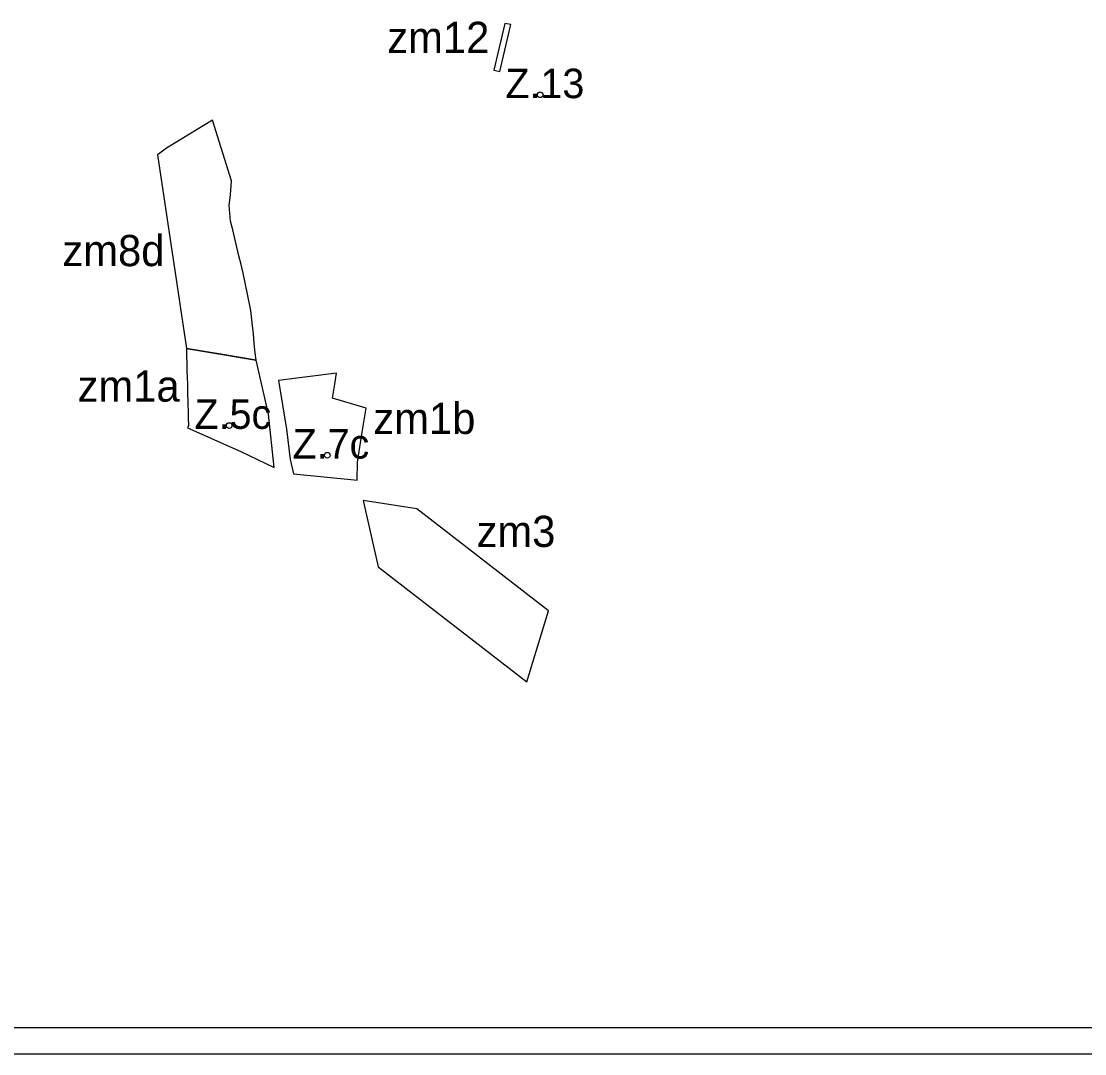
# Model space of a CAD drawing. Extents: x -555210 to -552521, y -1185897 to -1183927.
# Drawn here: x -554479 to -553865, y -1185897 to -1185302 of the extents above; entities that cross this region are included whole.
import ezdxf

# ---------------------------------------------------------------- set-up
doc = ezdxf.new("R2010")
doc.units = 0
for name, color, linetype in [('LEG_2b', 7, 'Continuous'), ('ram_5000', 7, 'Continuous'), ('stav_OV', 7, 'Continuous'), ('stav_PU', 7, 'Continuous'), ('stav_SV', 7, 'Continuous'), ('stav_SX', 7, 'Continuous'), ('stav_ZZ', 7, 'Continuous')]:
    doc.layers.add(name, color=color, linetype=linetype)

msp = doc.modelspace()

# ---------------------------------------------------------------- linework, layer by layer
at = {"layer": 'LEG_2b'}
for centre in [(-554179.27, -1185344.19), (-554358.57, -1185534.95), (-554302.04, -1185552.12)]:
    msp.add_circle(centre, 1.64, dxfattribs=at)
at = {"layer": 'ram_5000'}
for p, q in [((-554199.59, -1185303), (-554205.92, -1185330.05)), ((-554202.48, -1185330.72), (-554196.15, -1185303.69)), ((-554196.15, -1185303.69), (-554199.59, -1185303)), ((-554205.92, -1185330.05), (-554202.48, -1185330.72)), ((-554368.27, -1185358.89), (-554394.81, -1185374.96)), ((-554357.24, -1185393.87), (-554368.27, -1185358.89)), ((-554394.81, -1185374.96), (-554398.64, -1185377.82)), ((-554398.64, -1185377.82), (-554399.87, -1185378.78)), ((-554399.87, -1185378.78), (-554383.32, -1185490.61)), ((-554358.1, -1185403.56), (-554357.73, -1185399.4)), ((-554357.73, -1185399.4), (-554357.24, -1185393.87)), ((-554358.55, -1185407.8), (-554358.1, -1185403.56)), ((-554358.24, -1185412.39), (-554358.55, -1185407.8)), ((-554357.86, -1185417.02), (-554358.24, -1185412.39)), ((-554356.48, -1185422.06), (-554357.86, -1185417.02)), ((-554355.39, -1185427.08), (-554356.48, -1185422.06)), ((-554354.3, -1185432.1), (-554355.39, -1185427.08)), ((-554353.02, -1185437.14), (-554354.3, -1185432.1)), ((-554351.77, -1185442.03), (-554353.02, -1185437.14)), ((-554345.29, -1185475.74), (-554346.15, -1185468.55)), ((-554344.6, -1185481.98), (-554345.29, -1185475.74)), ((-554344.16, -1185487.64), (-554344.6, -1185481.98)), ((-554371.71, -1185492.51), (-554383.32, -1185490.61)), ((-554383.32, -1185490.61), (-554371.71, -1185492.51)), ((-554343.59, -1185493), (-554344.16, -1185487.64)), ((-554361.11, -1185494.25), (-554371.71, -1185492.51)), ((-554371.71, -1185492.51), (-554343.14, -1185497.2)), ((-554343.14, -1185497.2), (-554361.11, -1185494.25)), ((-554343.14, -1185497.2), (-554343.59, -1185493)), ((-554296.7, -1185504.81), (-554330.26, -1185509)), ((-554330.26, -1185509), (-554325.54, -1185537.09)), ((-554297.73, -1185511.18), (-554296.7, -1185504.81)), ((-554382.74, -1185511.12), (-554382.63, -1185515.01)), ((-554382.63, -1185515.01), (-554382.41, -1185522.77)), ((-554299.01, -1185519.14), (-554297.73, -1185511.18)), ((-554279.64, -1185524.91), (-554299.01, -1185519.14)), ((-554382.41, -1185522.77), (-554382.3, -1185526.64)), ((-554281.87, -1185538.72), (-554279.64, -1185524.91)), ((-554382.07, -1185534.97), (-554382.68, -1185536.3)), ((-554325.54, -1185537.09), (-554323.36, -1185554.5)), ((-554284.68, -1185556.1), (-554281.87, -1185538.72)), ((-554323.36, -1185554.5), (-554321.47, -1185562.78)), ((-554284.82, -1185566.4), (-554284.68, -1185556.1)), ((-554321.47, -1185562.78), (-554286.52, -1185566.23)), ((-554286.52, -1185566.23), (-554284.82, -1185566.4)), ((-554187.01, -1185682.72), (-554174.43, -1185641.89))]:
    msp.add_line(p, q, dxfattribs=at)
for points in [[(-554346.15, -1185468.55), (-554348.02, -1185459.19), (-554350.5, -1185447.06), (-554351.77, -1185442.03)], [(-554383.32, -1185490.61), (-554383.32, -1185490.77), (-554382.97, -1185503.16), (-554382.85, -1185507.17), (-554382.74, -1185511.12)], [(-554332.6, -1185559.09), (-554335.87, -1185528.47), (-554343.14, -1185497.2)], [(-554382.3, -1185526.64), (-554382.2, -1185530.48), (-554382.07, -1185534.97)], [(-554382.68, -1185536.3), (-554351.97, -1185549.89), (-554332.6, -1185559.09)], [(-554174.43, -1185641.89), (-554250.48, -1185583.07), (-554281.41, -1185578.27), (-554272.65, -1185616.49), (-554187.01, -1185682.72)]]:
    msp.add_lwpolyline(points, dxfattribs=at)
at = {"layer": 'stav_OV'}
for p, q in [((-553535.77, -1185882.32), (-555194.81, -1185882.32)), ((-555209.81, -1185897.32), (-552520.77, -1185897.32))]:
    msp.add_line(p, q, dxfattribs=at)
at = {"layer": 'stav_SX'}
for p, q in [((-554199.59, -1185303), (-554205.92, -1185330.05)), ((-554202.48, -1185330.72), (-554196.15, -1185303.69)), ((-554196.15, -1185303.69), (-554199.59, -1185303)), ((-554205.92, -1185330.05), (-554202.48, -1185330.72)), ((-554371.71, -1185492.51), (-554383.32, -1185490.61)), ((-554383.32, -1185490.61), (-554383.32, -1185490.77)), ((-554383.32, -1185490.77), (-554382.97, -1185503.16)), ((-554361.11, -1185494.25), (-554371.71, -1185492.51)), ((-554343.14, -1185497.2), (-554361.11, -1185494.25)), ((-554382.97, -1185503.16), (-554382.85, -1185507.17)), ((-554382.85, -1185507.17), (-554382.74, -1185511.12)), ((-554296.7, -1185504.81), (-554330.26, -1185509)), ((-554330.26, -1185509), (-554325.54, -1185537.09)), ((-554297.73, -1185511.18), (-554296.7, -1185504.81)), ((-554382.74, -1185511.12), (-554382.63, -1185515.01)), ((-554382.63, -1185515.01), (-554382.41, -1185522.77)), ((-554299.01, -1185519.14), (-554297.73, -1185511.18)), ((-554279.64, -1185524.91), (-554299.01, -1185519.14)), ((-554382.41, -1185522.77), (-554382.3, -1185526.64)), ((-554382.3, -1185526.64), (-554382.2, -1185530.48)), ((-554281.87, -1185538.72), (-554279.64, -1185524.91)), ((-554382.2, -1185530.48), (-554382.07, -1185534.97)), ((-554382.07, -1185534.97), (-554382.68, -1185536.3)), ((-554325.54, -1185537.09), (-554323.36, -1185554.5)), ((-554284.68, -1185556.1), (-554281.87, -1185538.72)), ((-554323.36, -1185554.5), (-554321.47, -1185562.78)), ((-554284.82, -1185566.4), (-554284.68, -1185556.1)), ((-554321.47, -1185562.78), (-554286.52, -1185566.23)), ((-554286.52, -1185566.23), (-554284.82, -1185566.4))]:
    msp.add_line(p, q, dxfattribs=at)
for points in [[(-554332.6, -1185559.09), (-554335.87, -1185528.47), (-554343.14, -1185497.2)], [(-554382.68, -1185536.3), (-554351.97, -1185549.89), (-554332.6, -1185559.09)]]:
    msp.add_lwpolyline(points, dxfattribs=at)
at = {"layer": 'stav_ZZ'}
for p, q in [((-554199.59, -1185303), (-554205.92, -1185330.05)), ((-554202.48, -1185330.72), (-554196.15, -1185303.69)), ((-554196.15, -1185303.69), (-554199.59, -1185303)), ((-554205.92, -1185330.05), (-554202.48, -1185330.72)), ((-554371.71, -1185492.51), (-554383.32, -1185490.61)), ((-554383.32, -1185490.61), (-554383.32, -1185490.77)), ((-554383.32, -1185490.77), (-554382.97, -1185503.16)), ((-554361.11, -1185494.25), (-554371.71, -1185492.51)), ((-554343.14, -1185497.2), (-554361.11, -1185494.25)), ((-554382.97, -1185503.16), (-554382.85, -1185507.17)), ((-554382.85, -1185507.17), (-554382.74, -1185511.12)), ((-554296.7, -1185504.81), (-554330.26, -1185509)), ((-554330.26, -1185509), (-554325.54, -1185537.09)), ((-554297.73, -1185511.18), (-554296.7, -1185504.81)), ((-554382.74, -1185511.12), (-554382.63, -1185515.01)), ((-554382.63, -1185515.01), (-554382.41, -1185522.77)), ((-554299.01, -1185519.14), (-554297.73, -1185511.18)), ((-554279.64, -1185524.91), (-554299.01, -1185519.14)), ((-554382.41, -1185522.77), (-554382.3, -1185526.64)), ((-554382.3, -1185526.64), (-554382.2, -1185530.48)), ((-554281.87, -1185538.72), (-554279.64, -1185524.91)), ((-554382.2, -1185530.48), (-554382.07, -1185534.97)), ((-554382.07, -1185534.97), (-554382.68, -1185536.3)), ((-554325.54, -1185537.09), (-554323.36, -1185554.5)), ((-554284.68, -1185556.1), (-554281.87, -1185538.72)), ((-554323.36, -1185554.5), (-554321.47, -1185562.78)), ((-554284.82, -1185566.4), (-554284.68, -1185556.1)), ((-554321.47, -1185562.78), (-554286.52, -1185566.23)), ((-554286.52, -1185566.23), (-554284.82, -1185566.4))]:
    msp.add_line(p, q, dxfattribs=at)
for points in [[(-554332.6, -1185559.09), (-554335.87, -1185528.47), (-554343.14, -1185497.2)], [(-554382.68, -1185536.3), (-554351.97, -1185549.89), (-554332.6, -1185559.09)]]:
    msp.add_lwpolyline(points, dxfattribs=at)

# ---------------------------------------------------------------- texts
at = {"layer": 'stav_PU'}
for s, p in [('Z.13', (-554199.33, -1185346.12)), ('Z.5c', (-554378.59, -1185536.89)), ('Z.7c', (-554322.06, -1185554.05))]:
    msp.add_text(s, height=17, dxfattribs=at).set_placement(p)
at = {"layer": 'stav_SV'}
for s, p in [('zm12', (-554267.46, -1185320.04)), ('zm8d', (-554454.8, -1185443.02)), ('zm1a', (-554446.03, -1185521.16)), ('zm1b', (-554275.5, -1185539.86)), ('zm3', (-554215.99, -1185605))]:
    msp.add_text(s, height=18, dxfattribs=at).set_placement(p)

doc.saveas('drawing.dxf')
